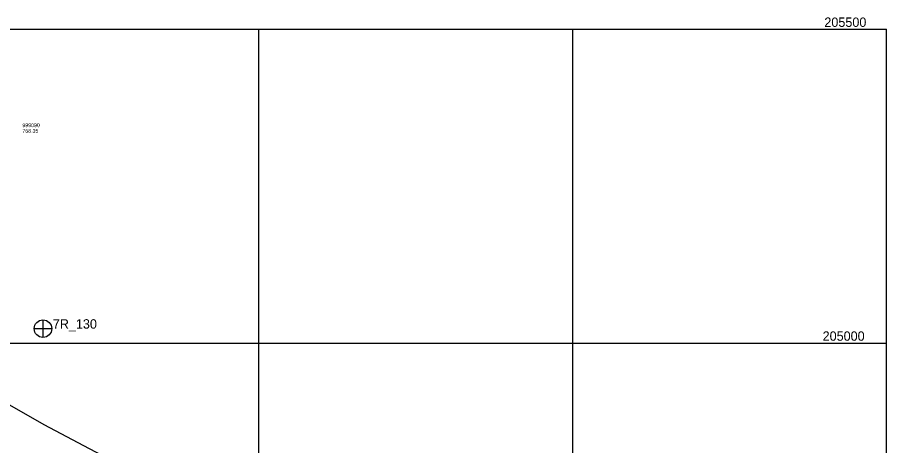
# Model space of a CAD drawing. Extents: x 591954 to 597000, y 198576 to 213500.
# Drawn here: x 595615 to 597000, y 204837 to 205519 of the extents above; entities that cross this region are included whole.
import ezdxf

# ---------------------------------------------------------------- set-up
doc = ezdxf.new("R2010")
doc.units = 0
for name, color, linetype in [('Level 10', 7, 'Continuous'), ('Level 4', 7, 'Continuous'), ('Level 6', 7, 'Continuous')]:
    doc.layers.add(name, color=color, linetype=linetype)

msp = doc.modelspace()

# ---------------------------------------------------------------- linework, layer by layer
at = {"layer": 'Level 10'}
for p, q in [((595000, 205500), (597000, 205500)), ((595000, 205500), (597000, 205500)), ((595000, 205500), (597000, 205500)), ((596000, 204000), (596000, 205500)), ((596000, 204000), (596000, 205500)), ((596000, 204000), (596000, 205500)), ((596500, 204000), (596500, 205500)), ((596500, 204000), (596500, 205500)), ((596500, 204000), (596500, 205500)), ((597000, 204000), (597000, 205500)), ((597000, 204000), (597000, 205500)), ((597000, 204000), (597000, 205500)), ((595000, 205000), (597000, 205000)), ((595000, 205000), (597000, 205000)), ((595000, 205000), (597000, 205000))]:
    msp.add_line(p, q, dxfattribs=at)
at = {"layer": 'Level 4'}
for p, q in [((595655.9, 205037.1), (595655.8, 205009.3)), ((595655.9, 205037.1), (595655.8, 205009.3)), ((595655.9, 205037.1), (595655.8, 205009.3)), ((595642, 205023.1), (595669.9, 205023.1)), ((595642, 205023.1), (595669.9, 205023.1)), ((595642, 205023.1), (595669.9, 205023.1))]:
    msp.add_line(p, q, dxfattribs=at)
msp.add_lwpolyline([(596451.1, 204145.5), (596525.3, 204456.3), (596301.7, 204553), (596061, 204676.8), (595803.6, 204793), (595657.9, 204869.8), (595496, 204962.2), (595284.7, 205098.9)], dxfattribs=at)
msp.add_lwpolyline([(596451.1, 204145.5), (596525.3, 204456.3), (596301.7, 204553), (596061, 204676.8), (595803.6, 204793), (595657.9, 204869.8), (595496, 204962.2), (595284.7, 205098.9)], dxfattribs=at)
msp.add_lwpolyline([(596451.1, 204145.5), (596525.3, 204456.3), (596301.7, 204553), (596061, 204676.8), (595803.6, 204793), (595657.9, 204869.8), (595496, 204962.2), (595284.7, 205098.9)], dxfattribs=at)
msp.add_circle((595655.9, 205023.1), 14, dxfattribs=at)
msp.add_circle((595655.9, 205023.1), 14, dxfattribs=at)
msp.add_circle((595655.9, 205023.1), 14, dxfattribs=at)

# ---------------------------------------------------------------- texts
at = {"layer": 'Level 10'}
for s, p in [(' 205500 ', (596895.2, 205503.8)), (' 205500 ', (596895.2, 205503.8)), (' 205500 ', (596895.2, 205503.8)), (' 205000 ', (596892.5, 205003.8)), (' 205000 ', (596892.5, 205003.8)), (' 205000 ', (596892.5, 205003.8))]:
    msp.add_text(s, height=15, dxfattribs=at).set_placement(p)
at = {"layer": 'Level 4'}
msp.add_text('7R_130', height=15, dxfattribs=at).set_placement((595671.6, 205023.1))
msp.add_text('7R_130', height=15, dxfattribs=at).set_placement((595671.6, 205023.1))
msp.add_text('7R_130', height=15, dxfattribs=at).set_placement((595671.6, 205023.1))
at = {"layer": 'Level 6'}
for s, p in [('999090', (595623.2, 205344.1)), ('999090', (595623.2, 205344.1)), ('999090', (595623.2, 205344.1)), ('768.35', (595623.2, 205335.1)), ('768.35', (595623.2, 205335.1)), ('768.35', (595623.2, 205335.1))]:
    msp.add_text(s, height=6, dxfattribs=at).set_placement(p)

doc.saveas('drawing.dxf')
